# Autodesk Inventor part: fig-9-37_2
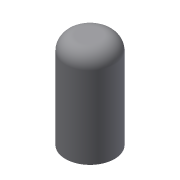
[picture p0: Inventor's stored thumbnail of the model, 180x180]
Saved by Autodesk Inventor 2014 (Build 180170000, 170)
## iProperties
Created: 2013-03
Part Number: fig-9-37_2
Material: Generic
Document SubType Name: Modeling
Designer: CADCIM
Density: 1 g/cm^3
Appearance: Default
Author: CADCIM
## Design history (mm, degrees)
sketch "Sketch1"
  geometry: C1 r 9 at (0, 0); 1 further point
  constraints: 1 centre point, 1 coincident
  dimensions: "d0" = 18 diameter of C1
extrude "Extrusion1" new body sketch "Sketch1" distance "d2" = 35; taper "d3" = 0 deg
fillet "Fillet1" dims "d4" = 5
body "Solid1"
